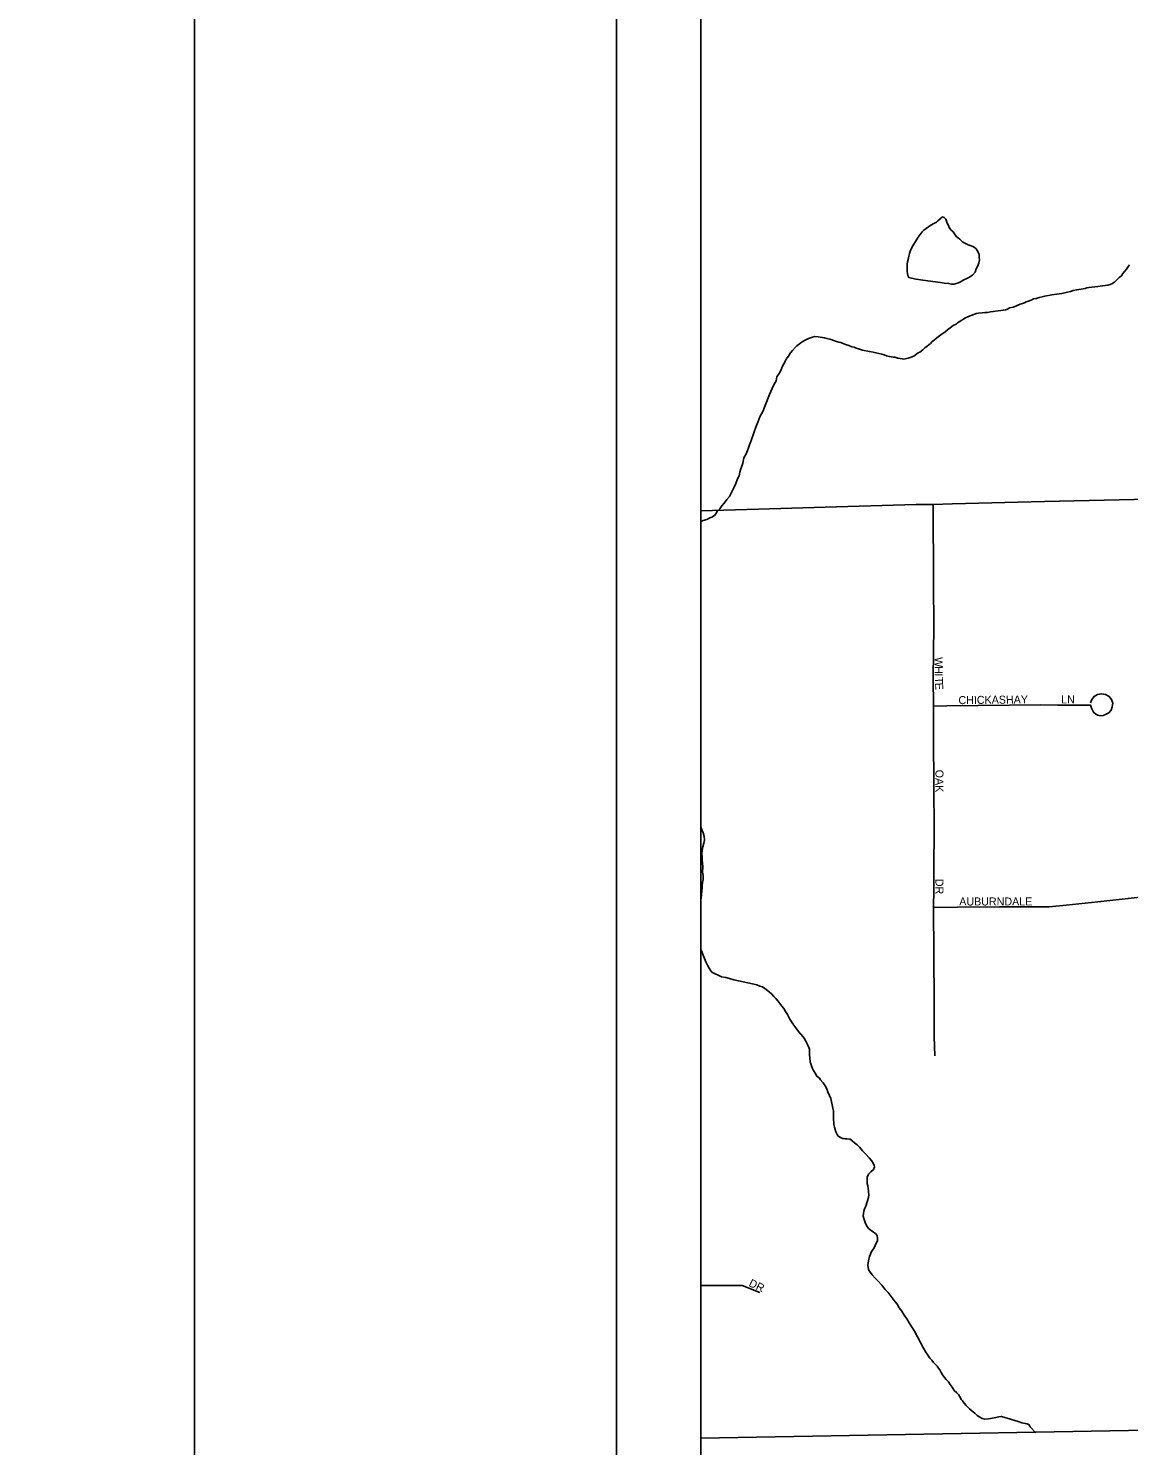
# Model space of a CAD drawing. Extents: x -10.1 to 68, y -9.5 to 29.2.
# Drawn here: x 1.303 to 2.607, y 16.786 to 18.464 of the extents above; entities that cross this region are included whole.
import ezdxf

# ---------------------------------------------------------------- set-up
doc = ezdxf.new("R2010")
doc.units = 0
for name, color, linetype in [('GM_X_Adjacent_County', 7, 'Continuous'), ('GM_X_Minor_Lake', 7, 'Continuous'), ('GM_X_Minor_River', 7, 'Continuous'), ('GM_X_Township_Road', 7, 'Continuous'), ('GM_X_Township_Subdivision', 7, 'Continuous'), ('GM_X_Township_Subdivision_Text', 7, 'Continuous'), ('SH_Border', 7, 'Continuous'), ('SH_Data', 7, 'Continuous')]:
    doc.layers.add(name, color=color, linetype=linetype)

msp = doc.modelspace()

# ---------------------------------------------------------------- linework, layer by layer
at = {"layer": 'GM_X_Adjacent_County'}
for points in [[(2.1, 16.7954), (2.1, 14.1), (8.9, 14.1), (8.9, 16.8967)], [(8.9, 16.8967), (8.5023, 16.8904), (7.9665, 16.8821), (7.5233, 16.8774), (6.5083, 16.8667), (6.2435, 16.8638), (4.8206, 16.8372), (4.1632, 16.8285), (3.6875, 16.8223), (2.8045, 16.808), (2.1, 16.7954)]]:
    msp.add_lwpolyline(points, dxfattribs=at)
at = {"layer": 'GM_X_Minor_Lake'}
for points in [[(2.3859, 18.241), (2.3807, 18.2364), (2.3788, 18.2348), (2.3758, 18.2329), (2.3724, 18.2309), (2.3694, 18.229), (2.3668, 18.227), (2.3641, 18.2251), (2.3619, 18.2231), (2.3597, 18.2201), (2.3574, 18.217), (2.3552, 18.2139), (2.3508, 18.2066), (2.3489, 18.2032), (2.3478, 18.2001), (2.3471, 18.1974), (2.346, 18.1944), (2.3453, 18.1906), (2.3446, 18.1875), (2.3443, 18.1848), (2.3443, 18.1818), (2.3444, 18.1788), (2.3444, 18.1761), (2.3448, 18.1738), (2.3449, 18.1716), (2.3461, 18.1693), (2.3495, 18.1682), (2.3548, 18.1671), (2.3628, 18.1661), (2.3836, 18.1631)], [(2.3836, 18.1631), (2.388, 18.1624), (2.3933, 18.1621), (2.3967, 18.1614), (2.3998, 18.1614), (2.4024, 18.1622), (2.4051, 18.163), (2.4081, 18.1642), (2.4115, 18.1662), (2.4149, 18.1681), (2.4179, 18.1697), (2.4197, 18.1709), (2.4216, 18.172), (2.4246, 18.1755), (2.4261, 18.1793), (2.4279, 18.1828), (2.429, 18.1866), (2.4297, 18.19), (2.4296, 18.1931), (2.4296, 18.1957), (2.4292, 18.1976), (2.4272, 18.201), (2.4261, 18.2029), (2.4241, 18.2048), (2.4218, 18.2059), (2.4199, 18.2066), (2.4165, 18.2077), (2.4103, 18.211), (2.4084, 18.2125), (2.4065, 18.2144), (2.4046, 18.2159), (2.4026, 18.2173), (2.4011, 18.2196), (2.3987, 18.223), (2.396, 18.2256), (2.3941, 18.2282), (2.3933, 18.2305), (2.3921, 18.2328), (2.3913, 18.2347), (2.3901, 18.2381), (2.3882, 18.2403), (2.3859, 18.241)]]:
    msp.add_lwpolyline(points, dxfattribs=at)
at = {"layer": 'GM_X_Minor_River'}
for points in [[(2.4364, 18.1278), (2.4395, 18.1278), (2.4429, 18.1283), (2.4463, 18.1287), (2.4489, 18.1291), (2.452, 18.1296), (2.455, 18.13), (2.458, 18.1304), (2.4607, 18.1308), (2.463, 18.1316), (2.4656, 18.1332), (2.4698, 18.134), (2.4728, 18.1352), (2.4754, 18.1364), (2.4781, 18.1376), (2.4807, 18.1384), (2.483, 18.1392), (2.4852, 18.1404), (2.4879, 18.1412), (2.4909, 18.1424), (2.4939, 18.1439), (2.4969, 18.1444), (2.5007, 18.1456), (2.5041, 18.1464), (2.5072, 18.1472), (2.5155, 18.1485), (2.5242, 18.1497), (2.5273, 18.1502), (2.5341, 18.1518), (2.5375, 18.1526), (2.5409, 18.1538), (2.545, 18.1546), (2.5477, 18.1551), (2.5503, 18.1555), (2.5526, 18.1559), (2.5549, 18.1563), (2.5572, 18.1567), (2.5594, 18.1572), (2.5629, 18.1576), (2.5701, 18.1585), (2.5727, 18.1589), (2.5757, 18.1593), (2.5788, 18.1597), (2.5818, 18.1602), (2.5845, 18.161), (2.5867, 18.1618), (2.5897, 18.1637), (2.5935, 18.1672), (2.5953, 18.1691), (2.598, 18.1711), (2.5998, 18.1738), (2.6021, 18.1765), (2.6039, 18.1788), (2.6054, 18.1815), (2.6076, 18.1842)], [(2.1629, 17.9865), (2.1651, 17.9919), (2.1672, 17.998), (2.1698, 18.0041), (2.1735, 18.0114), (2.1753, 18.0156), (2.1768, 18.0194), (2.1811, 18.0305), (2.1826, 18.034), (2.1844, 18.0378), (2.1859, 18.0412), (2.1874, 18.0439), (2.1889, 18.047), (2.1899, 18.0516), (2.1925, 18.0554), (2.1944, 18.0592), (2.1958, 18.0623), (2.1973, 18.0658), (2.1988, 18.0681), (2.1999, 18.07), (2.201, 18.0723), (2.2021, 18.0742), (2.2036, 18.0761), (2.2062, 18.08), (2.2084, 18.0827), (2.2118, 18.0865), (2.2136, 18.0881), (2.2166, 18.0908), (2.22, 18.0931), (2.2242, 18.0955), (2.2275, 18.097), (2.2298, 18.0978), (2.2321, 18.0986), (2.2347, 18.0991), (2.2389, 18.0987), (2.2412, 18.0984), (2.2439, 18.0981), (2.2465, 18.0977), (2.2492, 18.097), (2.2526, 18.0963), (2.2553, 18.0952), (2.258, 18.0941), (2.2607, 18.0934), (2.2633, 18.0927), (2.2656, 18.092), (2.2683, 18.0909), (2.271, 18.0898), (2.2752, 18.0887), (2.2786, 18.0872), (2.2813, 18.0865), (2.284, 18.0854), (2.2867, 18.0847), (2.2889, 18.084), (2.2912, 18.0832), (2.2996, 18.0815), (2.3038, 18.0808), (2.3072, 18.0801), (2.3107, 18.079), (2.3141, 18.0783), (2.3168, 18.0776), (2.3198, 18.0765), (2.3229, 18.0758), (2.3256, 18.0751), (2.3279, 18.0747), (2.3298, 18.0747), (2.3332, 18.0737), (2.3359, 18.0733), (2.3381, 18.073), (2.3404, 18.0726), (2.3435, 18.0731), (2.3454, 18.0735), (2.3491, 18.0747), (2.3522, 18.0762), (2.3555, 18.0786), (2.3574, 18.0798), (2.3593, 18.0809), (2.3627, 18.0836), (2.3653, 18.086), (2.3679, 18.0879), (2.3698, 18.0895), (2.3717, 18.091), (2.3739, 18.0933), (2.3765, 18.0953), (2.3795, 18.0976), (2.3825, 18.0999), (2.3855, 18.1023), (2.3889, 18.1046), (2.3919, 18.1073), (2.3953, 18.1096), (2.3987, 18.1124), (2.4021, 18.1139), (2.4039, 18.1155), (2.4058, 18.1167), (2.4133, 18.1213), (2.4167, 18.1229), (2.4201, 18.1241), (2.4232, 18.1253), (2.4258, 18.1265), (2.4288, 18.1269), (2.433, 18.1274), (2.4364, 18.1278)], [(2.1, 17.8802), (2.1027, 17.8814), (2.1068, 17.8826), (2.1087, 17.8834), (2.1106, 17.8845), (2.1129, 17.8853), (2.1159, 17.8873), (2.1174, 17.8892), (2.1192, 17.8923), (2.1222, 17.8954), (2.1248, 17.8988), (2.1274, 17.9019), (2.1308, 17.9065), (2.1337, 17.91), (2.1363, 17.9146), (2.1389, 17.92), (2.1411, 17.9253), (2.1433, 17.9307), (2.1451, 17.9345), (2.1462, 17.9387), (2.1473, 17.9425), (2.1483, 17.946), (2.1494, 17.9494), (2.1509, 17.9555), (2.1534, 17.9605), (2.1553, 17.9643), (2.1564, 17.9674), (2.1574, 17.9712), (2.1589, 17.975), (2.1604, 17.9785), (2.1614, 17.9819), (2.1629, 17.9865)], [(2.1, 17.5184), (2.1003, 17.5175), (2.1027, 17.5118), (2.1039, 17.5073), (2.104, 17.5035), (2.1033, 17.4997), (2.1022, 17.4951), (2.1015, 17.4909), (2.1012, 17.4871), (2.1013, 17.4833), (2.1014, 17.4795), (2.1018, 17.4757), (2.1022, 17.4715), (2.102, 17.4654), (2.1024, 17.4613), (2.1025, 17.4567), (2.1018, 17.4529), (2.1015, 17.4495), (2.1015, 17.4464), (2.1012, 17.443), (2.1005, 17.4388), (2.1002, 17.4342), (2.1, 17.4334)], [(2.1, 17.3738), (2.1005, 17.3723), (2.1025, 17.367), (2.104, 17.3632), (2.1056, 17.3591), (2.1076, 17.3553), (2.1096, 17.3515), (2.1115, 17.3485), (2.1134, 17.3466), (2.1154, 17.3455), (2.1177, 17.3444), (2.1196, 17.3437), (2.1219, 17.3426), (2.1245, 17.3415), (2.1295, 17.3404), (2.1337, 17.3394), (2.139, 17.3379), (2.1444, 17.3365), (2.1612, 17.333), (2.1661, 17.3319), (2.1696, 17.3304), (2.173, 17.3294), (2.1757, 17.3275), (2.1788, 17.3253), (2.1807, 17.3234), (2.1834, 17.3212), (2.1861, 17.3182), (2.1888, 17.3155), (2.1911, 17.3129), (2.1935, 17.3099), (2.1958, 17.3065), (2.1981, 17.3039), (2.2001, 17.3005), (2.2024, 17.2968), (2.2052, 17.2911), (2.2087, 17.2858), (2.2122, 17.2809), (2.2157, 17.2768), (2.2184, 17.2734), (2.2211, 17.2704), (2.2227, 17.2678), (2.2242, 17.2652), (2.2254, 17.2629), (2.2266, 17.2603), (2.2278, 17.2576), (2.2286, 17.2557), (2.2286, 17.2519), (2.2287, 17.2489), (2.2291, 17.2455), (2.2292, 17.2409), (2.2304, 17.2371), (2.2316, 17.2337), (2.2332, 17.2303), (2.2351, 17.2273), (2.2371, 17.2236), (2.2402, 17.2213), (2.2417, 17.2195), (2.2448, 17.2157), (2.2464, 17.2134), (2.2479, 17.2112), (2.2491, 17.2085), (2.2503, 17.2051), (2.2523, 17.201), (2.2539, 17.1972), (2.2563, 17.1859), (2.2568, 17.1828), (2.2568, 17.179), (2.2569, 17.1756), (2.2569, 17.1722), (2.2574, 17.1691), (2.2574, 17.1665), (2.2582, 17.1635), (2.259, 17.1608), (2.2598, 17.1578), (2.2614, 17.1548), (2.2626, 17.1529), (2.266, 17.1507), (2.2679, 17.1499), (2.2702, 17.1496), (2.2729, 17.1496), (2.2767, 17.1493), (2.279, 17.1471), (2.2817, 17.1448), (2.2848, 17.1426), (2.2879, 17.1396), (2.2914, 17.1355), (2.2952, 17.1314), (2.2991, 17.1272), (2.3018, 17.1239), (2.3038, 17.1209), (2.3053, 17.1182), (2.3057, 17.1163), (2.3043, 17.1133), (2.3013, 17.1105), (2.2983, 17.1078), (2.2968, 17.1044), (2.2969, 17.1006), (2.2969, 17.0968)], [(2.2969, 17.0968), (2.2978, 17.0938), (2.2982, 17.0903), (2.2986, 17.0885), (2.2986, 17.0862), (2.2987, 17.0835), (2.2984, 17.0801), (2.2951, 17.0698), (2.294, 17.0675), (2.2933, 17.0656), (2.2926, 17.0614), (2.2923, 17.0579), (2.2931, 17.0541), (2.2943, 17.0504), (2.2962, 17.047), (2.2986, 17.0436), (2.3017, 17.041), (2.3044, 17.0391), (2.3067, 17.0376), (2.3086, 17.035), (2.309, 17.032), (2.3091, 17.0289), (2.3076, 17.0259), (2.3065, 17.0232), (2.305, 17.0205), (2.3032, 17.0178), (2.3017, 17.0155), (2.3006, 17.0132), (2.2995, 17.0105), (2.2988, 17.0071), (2.2981, 17.0029), (2.2978, 16.9995), (2.2982, 16.9972), (2.2986, 16.9953), (2.2994, 16.9934), (2.3006, 16.9912), (2.3029, 16.9885), (2.3064, 16.9848), (2.3099, 16.981), (2.3141, 16.9762), (2.318, 16.9713), (2.3219, 16.9676), (2.3254, 16.9631), (2.3277, 16.9597), (2.33, 16.9567), (2.3324, 16.9537), (2.3347, 16.9495), (2.3378, 16.9454), (2.3406, 16.9409), (2.3437, 16.9364), (2.3464, 16.9318), (2.3495, 16.9273), (2.353, 16.9221), (2.3636, 16.9017), (2.3664, 16.8972), (2.3687, 16.8934), (2.371, 16.89), (2.3734, 16.8874), (2.3753, 16.8848), (2.3776, 16.8825), (2.3796, 16.8803), (2.3815, 16.878), (2.3831, 16.8762), (2.3846, 16.8731), (2.3862, 16.8701), (2.3885, 16.8671), (2.3905, 16.8649), (2.3932, 16.8619), (2.3951, 16.8589), (2.3975, 16.8555), (2.3986, 16.8536), (2.3998, 16.8517), (2.4029, 16.8491), (2.4052, 16.8469), (2.4064, 16.845), (2.4072, 16.8431), (2.4083, 16.8412), (2.4099, 16.8393), (2.4118, 16.8367), (2.4142, 16.8341), (2.418, 16.83), (2.4211, 16.8274), (2.4242, 16.8247), (2.4273, 16.8221), (2.4303, 16.8203), (2.433, 16.8184), (2.4361, 16.8177), (2.4406, 16.8182), (2.4471, 16.8194), (2.4528, 16.8206), (2.4558, 16.8211), (2.46, 16.8196), (2.4627, 16.8189), (2.4757, 16.8149), (2.4802, 16.8135), (2.484, 16.8128), (2.4863, 16.8121), (2.4886, 16.811), (2.4898, 16.8087), (2.4966, 16.8017)]]:
    msp.add_lwpolyline(points, dxfattribs=at)
at = {"layer": 'GM_X_Township_Road'}
msp.add_lwpolyline([(3.6584, 17.9291), (3.6348, 17.9286), (3.5569, 17.9274), (3.4652, 17.9257), (3.3805, 17.9243), (3.3033, 17.9214), (3.2228, 17.9197), (3.1564, 17.919), (3.134, 17.9187), (3.0925, 17.918), (3.0317, 17.9163), (2.8981, 17.9134), (2.8896, 17.9136), (2.8636, 17.9129), (2.8106, 17.9106), (2.7471, 17.9096), (2.6306, 17.9068), (2.5068, 17.9039), (2.3976, 17.9012), (2.3752, 17.9006), (2.3549, 17.9003), (2.2472, 17.8974), (2.1683, 17.895), (2.1, 17.8931)], dxfattribs=at)
at = {"layer": 'GM_X_Township_Subdivision'}
for points in [[(2.3752, 17.9006), (2.3756, 17.8079), (2.3757, 17.7557), (2.3752, 17.6951), (2.3755, 17.6617), (2.3756, 17.627), (2.3759, 17.5649), (2.3761, 17.517), (2.3759, 17.4676), (2.3759, 17.4446), (2.3756, 17.4235), (2.3761, 17.3123), (2.3763, 17.2709), (2.377, 17.248)], [(2.3755, 17.6617), (2.3912, 17.662), (2.5024, 17.6633), (2.5227, 17.6631), (2.5612, 17.6631), (2.5626, 17.6593), (2.5648, 17.6546), (2.5675, 17.6521), (2.57, 17.651), (2.5731, 17.6503), (2.5765, 17.6508), (2.5801, 17.6521), (2.583, 17.6539), (2.5857, 17.657), (2.5872, 17.6609), (2.5877, 17.6653), (2.5861, 17.6698), (2.5834, 17.673), (2.5792, 17.6756), (2.5742, 17.6765), (2.5695, 17.6756), (2.5657, 17.6732), (2.563, 17.6696), (2.5614, 17.6658)], [(2.3756, 17.4235), (2.4039, 17.4237), (2.4534, 17.4242), (2.4902, 17.4242), (2.5124, 17.4242), (2.5325, 17.426), (2.57, 17.4302), (2.613, 17.4349), (2.648, 17.4387), (2.6861, 17.4428), (2.7484, 17.4495), (2.7645, 17.4508), (2.795, 17.4515), (2.8566, 17.4529), (2.8995, 17.4533)], [(2.1, 16.9761), (2.1488, 16.9761), (2.1696, 16.9677)]]:
    msp.add_lwpolyline(points, dxfattribs=at)
at = {"layer": 'SH_Border'}
for points in [[(0.5, 21.5), (1.5, 21.5), (1.5, 0.5), (0.5, 0.5)], [(1.5, 21.5), (33.5, 21.5), (33.5, 0.5), (1.5, 0.5)]]:
    msp.add_lwpolyline(points, close=True, dxfattribs=at)
at = {"layer": 'SH_Data'}
for p, q in [((2, 21), (2, 14)), ((2.1, 20.9), (2.1, 14.1))]:
    msp.add_line(p, q, dxfattribs=at)

# ---------------------------------------------------------------- texts
at = {"layer": 'GM_X_Township_Subdivision_Text'}
for s, rotation, p in [('W', 270.0336, (2.3768, 17.7198)), ('H', 270.037, (2.3768, 17.709)), ('I', 270.582, (2.3768, 17.7005)), ('T', 272.4696, (2.3769, 17.696)), ('E', 273.5096, (2.3772, 17.6892)), ('CHICKASHAY', 0.6317, (2.405, 17.6641)), ('LN', 0, (2.5267, 17.6649)), ('OAK', 270, (2.3777, 17.5865)), ('DR', 270, (2.3777, 17.4573)), ('AUBURNDALE', 0, (2.4059, 17.4258)), ('DR', 334.7927, (2.1558, 16.9756))]:
    msp.add_text(s, height=0.00947, rotation=rotation, dxfattribs=at).set_placement(p)

doc.saveas('drawing.dxf')
